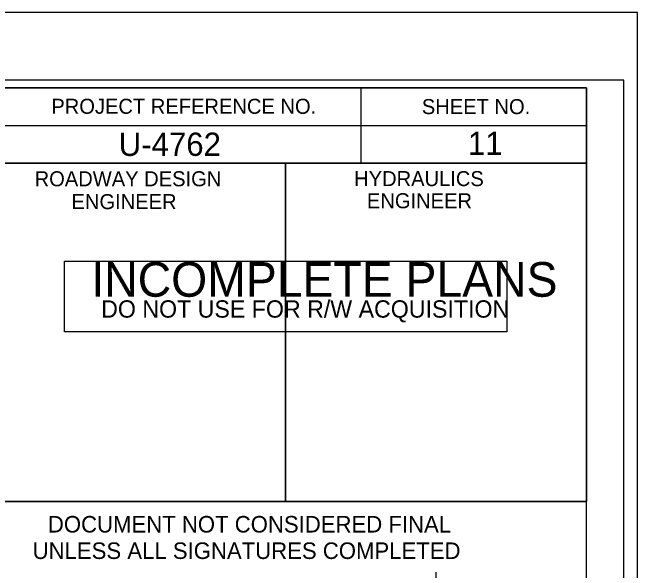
# Model space of a CAD drawing. Extents: x 2367101 to 2368930, y 803279 to 808979.
# Drawn here: x 2368577.2 to 2368785, y 804193.5 to 804379 of the extents above; entities that cross this region are included whole.
import ezdxf

# ---------------------------------------------------------------- set-up
doc = ezdxf.new("R2010")
doc.units = 0
for name, color, linetype in [('Old_Level_11', 7, 'Continuous'), ('Old_Level_15', 7, 'Continuous'), ('Old_Level_20', 7, 'Continuous'), ('Old_Level_4', 7, 'Continuous'), ('Old_Level_6', 7, 'Continuous'), ('Old_Level_9', 7, 'Continuous'), ('Plan Sheet CELL', 7, 'Continuous'), ('Plot Label CELL', 7, 'Continuous')]:
    doc.layers.add(name, color=color, linetype=linetype)

msp = doc.modelspace()

# ---------------------------------------------------------------- linework, layer by layer
at = {"layer": 'Old_Level_11'}
for points in [[(2368317.97, 803853.98), (2368367.97, 803853.98), (2368367.97, 804353.98), (2368417.97, 804353.98), (2368417.97, 803853.98), (2368467.97, 803853.98), (2368467.97, 804353.98), (2368517.97, 804353.98), (2368517.97, 803853.98), (2368567.97, 803853.98), (2368567.97, 804353.98), (2368594.27, 804353.98)], [(2368717.97, 804192.93), (2368717.97, 803853.98), (2368767.97, 803853.98), (2368767.97, 804203.98)]]:
    msp.add_lwpolyline(points, dxfattribs=at)
at = {"layer": 'Old_Level_15'}
msp.add_line((2368784.97, 804378.98), (2367100.97, 804378.98), dxfattribs=at)
at = {"layer": 'Old_Level_20'}
msp.add_lwpolyline([(2368594.49, 804272.78), (2368594.49, 804296.28), (2368741.49, 804296.28), (2368741.49, 804272.78)], close=True, dxfattribs=at)
at = {"layer": 'Old_Level_4'}
msp.add_lwpolyline([(2367113.97, 803301.43), (2368780.47, 803301.43), (2368780.47, 804356.53), (2367113.97, 804356.53)], close=True, dxfattribs=at)
at = {"layer": 'Old_Level_6'}
msp.add_lwpolyline([(2367100.97, 803278.98), (2368784.97, 803278.98), (2368784.97, 804378.98), (2367100.97, 804378.98)], close=True, dxfattribs=at)
at = {"layer": 'Old_Level_9'}
for p, q in [((2368692.97, 804353.93), (2368692.97, 804328.93)), ((2368567.92, 804341.43), (2368767.97, 804341.43)), ((2368667.97, 804328.93), (2368667.97, 804216.48))]:
    msp.add_line(p, q, dxfattribs=at)
for points in [[(2368767.97, 804353.98), (2367267.97, 804353.98), (2367267.97, 803303.98), (2368767.97, 803303.98)], [(2368567.92, 804353.98), (2368767.97, 804353.98), (2368767.97, 804328.93), (2368567.92, 804328.93)], [(2368567.92, 804328.93), (2368667.97, 804328.93), (2368667.97, 804216.43), (2368567.92, 804216.43)], [(2368667.97, 804328.93), (2368767.97, 804328.93), (2368767.97, 804216.43), (2368667.97, 804216.43)]]:
    msp.add_lwpolyline(points, close=True, dxfattribs=at)
at = {"layer": 'Plan Sheet CELL'}
for p, q in [((2368567.92, 804216.43), (2368767.96, 804216.43)), ((2368567.92, 804216.43), (2368767.96, 804216.43)), ((2368767.96, 804216.42), (2368767.96, 804192.92)), ((2368767.96, 804216.42), (2368767.96, 804192.92))]:
    msp.add_line(p, q, dxfattribs=at)

# ---------------------------------------------------------------- texts
at = {"layer": 'Old_Level_20'}
for s, height, p in [('INCOMPLETE PLANS', 11.52, (2368603.44, 804284.48)), ('DO NOT USE FOR R/W ACQUISITION', 5.76, (2368606.69, 804277.53))]:
    msp.add_text(s, height=height, dxfattribs=at).set_placement(p)
at = {"layer": 'Old_Level_9'}
for s, height, p in [('PROJECT REFERENCE NO.', 5.0001, (2368590.14, 804345.3)), ('SHEET NO.', 5, (2368713.29, 804345.2)), ('ROADWAY DESIGN', 5.0001, (2368584.59, 804321.2)), ('HYDRAULICS', 5, (2368690.79, 804321.25)), ('ENGINEER', 5, (2368596.84, 804313.6)), ('ENGINEER', 5, (2368695.04, 804313.9))]:
    msp.add_text(s, height=height, dxfattribs=at).set_placement(p)
at = {"layer": 'Plan Sheet CELL'}
for s, p in [('DOCUMENT NOT CONSIDERED FINAL', (2368588.99, 804206.09)), ('DOCUMENT NOT CONSIDERED FINAL', (2368588.99, 804206.09)), ('UNLESS ALL SIGNATURES COMPLETED', (2368583.92, 804197.29)), ('UNLESS ALL SIGNATURES COMPLETED', (2368583.92, 804197.29))]:
    msp.add_text(s, height=5.5, dxfattribs=at).set_placement(p)
at = {"layer": 'Plot Label CELL'}
for s, p in [('U-4762', (2368612.52, 804331.3)), ('11', (2368728.6, 804331.6))]:
    msp.add_text(s, height=7.75, dxfattribs=at).set_placement(p)

doc.saveas('drawing.dxf')
